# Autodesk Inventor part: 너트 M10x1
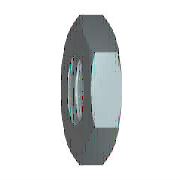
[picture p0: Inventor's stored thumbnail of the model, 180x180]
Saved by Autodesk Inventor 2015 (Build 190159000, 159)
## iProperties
Created: 2012-02
Part Number: 너트 M10x1
Material: 강철, 연강
Description: 6각 가는 너트 - 이중 모따기(부품 등급 A) - 정밀 나사산
Document SubType Name: Modeling
Standard: JIS B 1181
Designer: mduedu
Standards Organization: JIS
Language: ko-KR
Size Designation: M10x1
Categories: <MemberInstance><Categories><Category DisplayName="조임쇠" InternalName="e4da775c-781d-43d5-af7c-5136215cf5a6" Mnemonic="FSTN"><Category DisplayName="너트" InternalN
Density: 7.86 g/cm^3
Appearance: 강철
IsCustomPart: 1
Author: mduedu
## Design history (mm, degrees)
node "MSC_A1"
node "MSC_PT1"
node "MSC_PT2"
node "MSC_PF1"
body "Solid1"
sketch "스케치1"
  geometry: L1 (8, 4.619)-(8, -4.619); L2 (8, -4.619)-(0, -9.238); L3 (0, -9.238)-(-8, -4.619); L4 (-8, -4.619)-(-8, 4.619); L5 (-8, 4.619)-(0, 9.238); L6 (0, 9.238)-(8, 4.619); C1 r 8 at (0, 0); 2 further points
  constraints: 12 end point, 2 coincident, 1 centre point, 1 tangent, 1 vertical, 11 other
  dimensions: "d0" = 16 diameter of C1 (= ParS)
extrude "돌출1" new body sketch "스케치1" distance "d1" = 5 (= M); taper "d2" = 0 deg
sketch "스케치2"
  geometry: L1 (-8, 4.619)-(0, 9.238) reference; L2 (0, -9.238)-(-8, -4.619) reference; L3 (-8, 4.619)-(8, -4.619); L4 (-8, -4.619)-(8, 4.619); 1 further point
  constraints: 4 end point, 2 midpoint, 2 parallel
hole "구멍1" sketch "스케치2" diameter "d3" = 8.91747; stored, may be unused: countersink angle "d7" = 90 deg, drill point angle "d9" = 118 deg; dims "d4" = 6, "d5" = 4, "d6" = 2, "d8" = 8
chamfer "모따기1" distance "d10" = 0.5 (= 0.5 x PTC); stored, may be unused: second distance "d11" = 2, angle "d12" = 45 deg
revolve "회전1" stored, may be unused: angle "d15" = 90 deg
sketch "스케치3"
  geometry: L1 (-9.238, 5)-(-9.238, 4.285); L2 (-9.238, 4.285)-(-8, 5); L3 (-8, 5)-(-9.238, 5); L4 (-9.238, 0.715)-(-9.238, 0); L5 (-9.238, 0)-(-8, 0); L6 (-8, 0)-(-9.238, 0.715); L7 (0, 6)-(0, -1) reference; L8 (-4.619, 5)-(-9.238, 5) reference; L9 (-4.619, 0)-(-9.238, 0) reference; L10 (-9.238, 0)-(-9.238, 5) reference
  constraints: 12 end point, 4 collinear, 3 perpendicular, 2 equal length, 1 vertical
  dimensions: "d13" = 30 deg angle of L2 L3; "d14" = 8 distance from line of L2.end L7 (= 0.5 x ParS)
other parameters: "ParS" = 16 [user parameter; used in 2 equation terms], "M" = 5 [user parameter; used in 1 equation term], "PTC" = 1 [user parameter; used in 1 equation term], "d17" = 0, "d18" = 0, "d19" = 0, "d20" = 0, "d21" = 0, "d22" = 0, "d23" = 0
